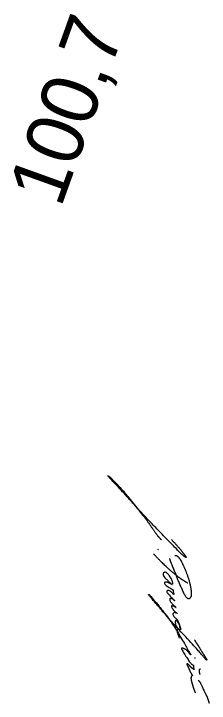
# Model space of a CAD drawing. Extents: x -545736 to -544888, y -1122892 to -1119128.
# Drawn here: x -545090.24 to -545078.22, y -1122725.59 to -1122683.23 of the extents above; entities that cross this region are included whole.
import ezdxf

# ---------------------------------------------------------------- set-up
doc = ezdxf.new("R2010")
doc.units = 0
doc.layers.add('Vrstva 19 - Staniceni', color=7, linetype='Continuous')
doc.layers.add('Vrstva 63', color=7, linetype='Continuous')

msp = doc.modelspace()

# ---------------------------------------------------------------- linework, layer by layer
at = {"layer": 'Vrstva 63'}
for points, degree in [([(-545080.549, -1122715.524), (-545080.149, -1122715.964), (-545079.79, -1122716.409), (-545079.662, -1122716.583), (-545079.616, -1122716.646), (-545079.68, -1122716.631), (-545079.85, -1122716.498), (-545080.269, -1122716.087), (-545082.272, -1122714.025), (-545083.593, -1122712.538), (-545084.429, -1122711.661), (-545084.461, -1122711.611), (-545084.401, -1122711.633), (-545084.246, -1122711.774), (-545083.776, -1122712.253), (-545083.284, -1122712.816), (-545082.067, -1122714.339), (-545081.676, -1122714.922), (-545081.329, -1122715.397), (-545081.16, -1122715.552)], 2), ([(-545079.542, -1122718.22), (-545079.813, -1122718.057), (-545080.185, -1122717.791), (-545080.545, -1122717.496), (-545081.094, -1122716.995), (-545081.649, -1122716.418)], 2), ([(-545081.347, -1122716.17), (-545081.354, -1122716.167), (-545081.363, -1122716.16), (-545081.374, -1122716.155)], 2), ([(-545080.331, -1122716.512), (-545080.246, -1122716.509), (-545080.168, -1122716.562), (-545080.07, -1122716.673), (-545079.945, -1122716.852), (-545079.775, -1122717.211), (-545079.615, -1122717.594), (-545079.479, -1122717.987), (-545079.374, -1122718.413), (-545079.327, -1122718.742), (-545079.322, -1122718.98), (-545079.365, -1122719.083), (-545079.426, -1122719.163), (-545079.511, -1122719.188), (-545079.668, -1122719.075), (-545079.919, -1122718.533), (-545080.154, -1122717.997), (-545080.353, -1122717.463), (-545080.582, -1122716.936), (-545080.654, -1122716.706)], 2), ([(-545080.469, -1122718.28), (-545080.463, -1122718.193), (-545080.488, -1122718.067), (-545080.588, -1122717.879), (-545080.738, -1122717.665), (-545080.873, -1122717.551), (-545080.936, -1122717.528), (-545081.006, -1122717.559), (-545081.058, -1122717.619), (-545081.052, -1122717.717), (-545081.006, -1122717.816), (-545080.887, -1122717.942), (-545080.769, -1122718.059), (-545080.623, -1122718.206), (-545080.546, -1122718.277), (-545080.478, -1122718.304), (-545080.557, -1122718.292), (-545080.722, -1122718.185), (-545080.902, -1122718.139), (-545080.961, -1122718.159), (-545080.99, -1122718.197), (-545080.968, -1122718.264), (-545080.86, -1122718.356), (-545080.753, -1122718.439), (-545080.654, -1122718.51), (-545080.548, -1122718.566), (-545080.428, -1122718.628), (-545080.444, -1122718.64), (-545080.443, -1122718.712), (-545080.429, -1122718.786), (-545080.41, -1122718.859), (-545080.386, -1122718.935), (-545080.426, -1122718.893), (-545080.496, -1122718.812), (-545080.571, -1122718.728), (-545080.663, -1122718.669), (-545080.749, -1122718.668), (-545080.815, -1122718.676), (-545080.839, -1122718.74), (-545080.808, -1122718.806), (-545080.747, -1122718.866), (-545080.66, -1122718.962), (-545080.594, -1122719.048), (-545080.501, -1122719.152), (-545080.395, -1122719.257), (-545080.319, -1122719.324), (-545080.42, -1122719.244), (-545080.521, -1122719.169), (-545080.584, -1122719.145), (-545080.625, -1122719.167), (-545080.647, -1122719.194), (-545080.659, -1122719.268), (-545080.593, -1122719.377), (-545080.534, -1122719.447), (-545080.461, -1122719.523), (-545080.36, -1122719.62), (-545080.287, -1122719.696), (-545080.243, -1122719.737), (-545080.321, -1122719.685), (-545080.431, -1122719.629), (-545080.511, -1122719.609), (-545080.558, -1122719.623), (-545080.539, -1122719.7), (-545080.469, -1122719.804), (-545080.396, -1122719.898), (-545080.333, -1122719.967), (-545080.262, -1122720.029), (-545080.196, -1122720.071), (-545080.165, -1122720.092), (-545080.245, -1122720.049), (-545080.333, -1122720.016), (-545080.411, -1122720.031), (-545080.451, -1122720.08), (-545080.458, -1122720.135), (-545080.422, -1122720.228), (-545080.377, -1122720.295), (-545080.274, -1122720.384), (-545080.222, -1122720.423), (-545080.165, -1122720.484), (-545080.128, -1122720.58), (-545080.082, -1122720.675), (-545080.039, -1122720.825), (-545080.009, -1122720.913), (-545079.975, -1122721.015), (-545079.973, -1122721.049), (-545079.987, -1122720.999), (-545080.019, -1122720.906), (-545080.06, -1122720.788), (-545080.091, -1122720.722), (-545080.128, -1122720.648), (-545080.163, -1122720.583), (-545080.204, -1122720.537), (-545080.245, -1122720.513), (-545080.299, -1122720.514), (-545080.321, -1122720.56), (-545080.31, -1122720.661), (-545080.294, -1122720.748), (-545080.254, -1122720.835), (-545080.198, -1122720.914), (-545080.159, -1122720.976), (-545080.142, -1122720.996)], 3), ([(-545079.126, -1122721.701), (-545079.087, -1122721.789), (-545078.998, -1122721.916), (-545078.893, -1122722.072), (-545078.72, -1122722.358), (-545078.536, -1122722.642), (-545078.444, -1122722.816), (-545078.381, -1122722.89), (-545078.36, -1122722.944), (-545078.398, -1122722.941), (-545078.494, -1122722.831), (-545078.73, -1122722.552), (-545079.087, -1122722.147), (-545079.879, -1122721.288), (-545080.437, -1122720.703), (-545081.05, -1122719.995), (-545081.708, -1122719.222), (-545081.969, -1122718.926), (-545081.951, -1122718.906), (-545081.899, -1122718.928), (-545081.775, -1122719.069), (-545081.505, -1122719.39), (-545081.07, -1122719.919), (-545080.464, -1122720.729), (-545079.858, -1122721.726), (-545079.502, -1122722.372), (-545079.379, -1122722.567), (-545079.349, -1122722.636), (-545079.395, -1122722.591), (-545079.527, -1122722.409), (-545079.673, -1122722.288), (-545079.82, -1122722.221), (-545079.9, -1122722.193), (-545079.927, -1122722.22), (-545079.908, -1122722.291), (-545079.783, -1122722.518), (-545079.59, -1122722.821), (-545079.434, -1122723.047), (-545079.336, -1122723.167), (-545079.278, -1122723.219), (-545079.213, -1122723.249), (-545079.179, -1122723.259), (-545079.204, -1122723.322), (-545079.193, -1122723.406), (-545079.174, -1122723.477), (-545079.144, -1122723.524), (-545079.203, -1122723.493), (-545079.283, -1122723.439), (-545079.396, -1122723.323), (-545079.485, -1122723.223), (-545079.536, -1122723.184), (-545079.578, -1122723.161), (-545079.606, -1122723.177), (-545079.58, -1122723.257), (-545079.495, -1122723.422), (-545079.403, -1122723.644), (-545079.321, -1122723.793), (-545079.275, -1122723.864), (-545079.248, -1122723.891), (-545079.293, -1122723.905), (-545079.341, -1122723.963), (-545079.348, -1122724.119), (-545079.302, -1122724.297), (-545079.222, -1122724.569), (-545079.138, -1122724.836), (-545079.071, -1122724.961)], 2), ([(-545080.142, -1122720.996), (-545080.125, -1122721.017), (-545080.097, -1122721.039), (-545080.047, -1122721.061), (-545079.973, -1122721.039), (-545079.975, -1122721.06), (-545080.029, -1122721.062), (-545080.109, -1122721.068), (-545080.155, -1122721.064), (-545080.178, -1122721.086), (-545080.202, -1122721.145), (-545080.191, -1122721.228), (-545080.157, -1122721.353), (-545080.109, -1122721.483), (-545080.07, -1122721.593)], 3), ([(-545079.07, -1122722.827), (-545079.09, -1122722.822), (-545079.118, -1122722.818), (-545079.13, -1122722.815)], 2), ([(-545078.773, -1122723.49), (-545078.797, -1122723.504), (-545078.835, -1122723.529), (-545078.845, -1122723.576), (-545078.845, -1122723.636), (-545078.843, -1122723.686), (-545078.826, -1122723.747), (-545078.804, -1122723.82)], 2), ([(-545078.889, -1122724.186), (-545078.848, -1122724.235), (-545078.783, -1122724.321), (-545078.764, -1122724.358), (-545078.707, -1122724.481), (-545078.531, -1122724.851), (-545078.407, -1122725.105), (-545078.354, -1122725.207), (-545078.313, -1122725.33), (-545078.274, -1122725.467), (-545078.243, -1122725.552), (-545078.223, -1122725.593)], 2)]:
    msp.add_open_spline(points, degree=degree, dxfattribs=at)

# ---------------------------------------------------------------- texts
at = {"layer": 'Vrstva 19 - Staniceni'}
msp.add_text('100,7', height=3.5, rotation=70.2244, dxfattribs=at).set_placement((-545087.356, -1122695.21))

doc.saveas('drawing.dxf')
